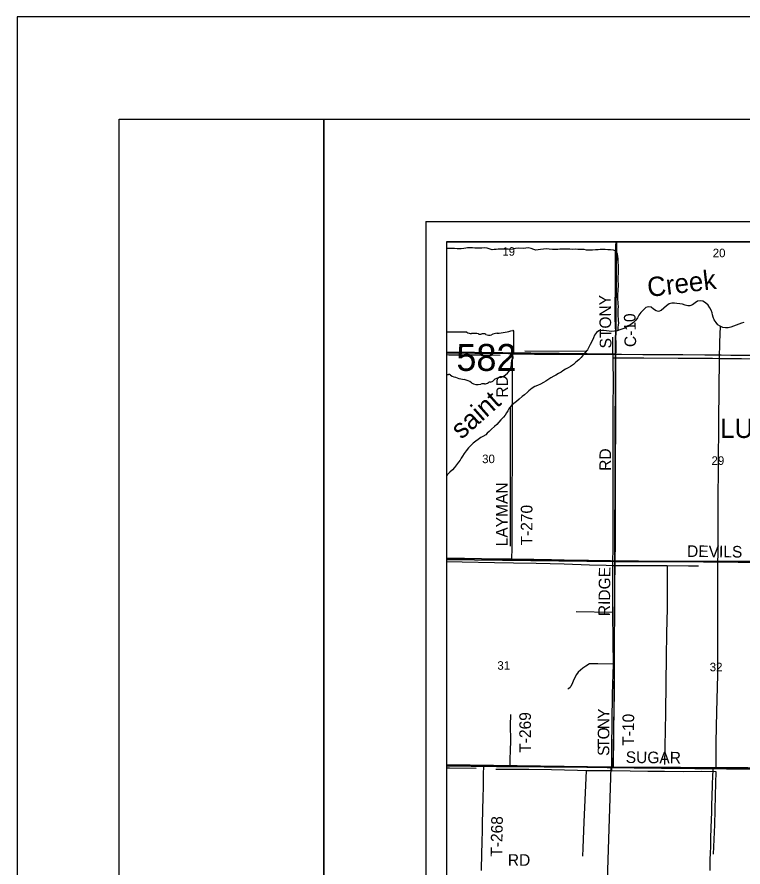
# Model space of a CAD drawing. Extents: x -8.3 to 42.1, y 0 to 22.
# Drawn here: x 0 to 3.551, y 17.841 to 22 of the extents above; entities that cross this region are included whole.
import ezdxf

# ---------------------------------------------------------------- set-up
doc = ezdxf.new("R2010")
doc.units = 0
for name, color, linetype in [('Default', 7, 'Continuous'), ('GM_X_Corporation_Text', 7, 'Continuous'), ('GM_X_County_Road', 7, 'Continuous'), ('GM_X_County_Road_Text', 7, 'Continuous'), ('GM_X_Major_River', 7, 'Continuous'), ('GM_X_Major_River_Text', 7, 'Continuous'), ('GM_X_Minor_River', 7, 'Continuous'), ('GM_X_Section', 7, 'Continuous'), ('GM_X_Section_Text', 7, 'Continuous'), ('GM_X_State_Location', 7, 'Continuous'), ('GM_X_State_Route', 7, 'Continuous'), ('GM_X_State_Shield', 7, 'Continuous'), ('GM_X_Township_Road', 7, 'Continuous'), ('GM_X_Township_Road_Text', 7, 'Continuous'), ('SH_Border', 7, 'Continuous'), ('SH_Cut_Line', 7, 'Continuous'), ('SH_Data', 7, 'Continuous')]:
    doc.layers.add(name, color=color, linetype=linetype)

msp = doc.modelspace()

# ---------------------------------------------------------------- linework, layer by layer
at = {"layer": 'Default'}
for points in [[(2.9318, 20.9), (2.1, 20.9), (2.1, 20.3595), (2.9276, 20.3504)], [(3.9394, 20.9), (2.9318, 20.9), (2.9276, 20.3504), (3.938, 20.3445)], [(2.1, 20.3595), (2.1, 19.3455), (2.9241, 19.3359), (2.9276, 20.3504)], [(2.1, 19.3455), (2.1, 18.3401), (2.9069, 18.3295), (2.9164, 18.3298), (2.9226, 18.6969), (2.9241, 19.3359)], [(2.1, 18.3401), (2.1, 17.3208), (2.8735, 17.321), (2.9069, 18.3295)]]:
    msp.add_lwpolyline(points, close=True, dxfattribs=at)
at = {"layer": 'GM_X_County_Road'}
for points in [[(2.9293, 20.3498), (2.9297, 20.3553), (2.9298, 20.3569), (2.9299, 20.3589), (2.9299, 20.387), (2.9299, 20.41), (2.9296, 20.4274), (2.9286, 20.4542), (2.9271, 20.4921), (2.9263, 20.5238), (2.9265, 20.612), (2.9267, 20.6475), (2.9269, 20.7003), (2.9271, 20.7843), (2.9273, 20.8247), (2.9277, 20.8396), (2.9293, 20.8787), (2.9301, 20.9)], [(2.1, 18.3366), (2.1679, 18.3356), (2.2208, 18.3346), (2.2836, 18.3338)], [(2.2836, 18.3338), (2.286, 18.3337), (2.3451, 18.3333), (2.413, 18.3327)], [(2.413, 18.3327), (2.4259, 18.3326), (2.5129, 18.3323), (2.5782, 18.3318), (2.6652, 18.3311), (2.7274, 18.3303), (2.7864, 18.3294), (2.8362, 18.3288), (2.8859, 18.328), (2.9185, 18.3276)], [(2.9185, 18.3276), (2.9325, 18.3274), (3.0195, 18.3264), (3.0662, 18.3259), (3.1532, 18.325), (3.234, 18.3242), (3.3148, 18.3234), (3.3583, 18.3229), (3.4054, 18.3223)], [(3.4054, 18.3223), (3.4174, 18.3222), (3.4702, 18.3219), (3.5199, 18.3217), (3.6194, 18.3209), (3.6878, 18.3206), (3.7468, 18.32), (3.7904, 18.3196), (3.8401, 18.319), (3.8898, 18.3182), (3.9079, 18.3179)]]:
    msp.add_lwpolyline(points, dxfattribs=at)
at = {"layer": 'GM_X_Major_River'}
for points in [[(3.5432, 20.5019), (3.531, 20.4968), (3.5172, 20.4917), (3.5038, 20.4867), (3.4908, 20.4827), (3.4779, 20.4795), (3.4653, 20.4783), (3.4525, 20.4804), (3.4386, 20.4875), (3.428, 20.493), (3.4192, 20.5058), (3.4103, 20.5188), (3.4049, 20.5319), (3.4024, 20.5433), (3.3999, 20.5529), (3.396, 20.5647), (3.3894, 20.5774), (3.3801, 20.5901), (3.3675, 20.6021), (3.3539, 20.6089), (3.3422, 20.6114), (3.3285, 20.6101), (3.3166, 20.602), (3.3035, 20.5908), (3.2913, 20.5865), (3.2818, 20.5867), (3.2689, 20.5907), (3.2546, 20.5944), (3.2417, 20.5962), (3.2281, 20.5987), (3.2152, 20.5993), (3.2023, 20.5992), (3.1893, 20.5957), (3.1763, 20.586), (3.1643, 20.5752), (3.1516, 20.5641), (3.1382, 20.5586), (3.1261, 20.5615), (3.1141, 20.5697), (3.1017, 20.5795), (3.0885, 20.5824), (3.0752, 20.5781), (3.0639, 20.5673), (3.0519, 20.5546), (3.0422, 20.5411), (3.0344, 20.5283), (3.0262, 20.5163), (3.0154, 20.5049), (3.0026, 20.4947), (2.9896, 20.4881), (2.9758, 20.4796), (2.9632, 20.4749), (2.9494, 20.4695), (2.9356, 20.4645), (2.9227, 20.462), (2.9094, 20.4615), (2.8961, 20.4622), (2.8836, 20.4639), (2.8696, 20.4661), (2.8598, 20.4663), (2.8465, 20.4639), (2.8338, 20.4569), (2.8244, 20.4434), (2.8196, 20.4309), (2.8145, 20.4185), (2.8042, 20.3982), (2.7975, 20.3846), (2.7901, 20.3722), (2.7792, 20.3587), (2.7691, 20.3464), (2.759, 20.3344), (2.7474, 20.3225), (2.7339, 20.3117), (2.7216, 20.3002), (2.7077, 20.2906), (2.6951, 20.284), (2.6832, 20.2766), (2.6701, 20.2681), (2.6611, 20.2621), (2.6484, 20.2551), (2.6353, 20.2477), (2.6255, 20.2432), (2.6115, 20.2346), (2.5972, 20.2254), (2.5872, 20.2184), (2.5745, 20.211), (2.5604, 20.2037), (2.5454, 20.1968), (2.5336, 20.1917), (2.5202, 20.184), (2.503, 20.1702), (2.4977, 20.1649), (2.4821, 20.1518), (2.4708, 20.1423), (2.4562, 20.1308), (2.4427, 20.1193), (2.4307, 20.1093), (2.418, 20.0989), (2.4071, 20.0854), (2.4, 20.073), (2.3949, 20.0628)], [(3.5549, 20.5055), (3.5432, 20.5019)], [(2.3949, 20.0628), (2.3879, 20.0516), (2.379, 20.0415), (2.3666, 20.0295), (2.3573, 20.0176), (2.3476, 20.006), (2.336, 19.9963), (2.3217, 19.9833), (2.3101, 19.9717), (2.3005, 19.9632), (2.2929, 19.9557), (2.2789, 19.9472), (2.2693, 19.9421), (2.2563, 19.9332), (2.2436, 19.9251), (2.2312, 19.9147), (2.2196, 19.9039), (2.208, 19.8916), (2.1975, 19.8777), (2.187, 19.8646), (2.1788, 19.8507), (2.1733, 19.8409), (2.1671, 19.8312), (2.16, 19.8214), (2.1402, 19.796), (2.1294, 19.784), (2.117, 19.7732), (2.1046, 19.7602), (2.1, 19.7542)]]:
    msp.add_lwpolyline(points, dxfattribs=at)
at = {"layer": 'GM_X_Minor_River'}
for points in [[(2.9408, 20.4663), (2.9412, 20.4816), (2.9423, 20.4919), (2.943, 20.504), (2.9429, 20.5143), (2.9417, 20.5238), (2.9405, 20.5364), (2.9401, 20.5482), (2.9407, 20.5687), (2.9415, 20.5839), (2.9411, 20.5965), (2.9398, 20.606), (2.9386, 20.6159), (2.9385, 20.6254), (2.9388, 20.6368), (2.9395, 20.6475), (2.9406, 20.6573), (2.9409, 20.6687), (2.9424, 20.6824), (2.9424, 20.6949), (2.9412, 20.7079), (2.9408, 20.7193), (2.9404, 20.7315), (2.9418, 20.7421), (2.9425, 20.7645), (2.9421, 20.7774), (2.9416, 20.7873), (2.9407, 20.7968), (2.9407, 20.8086), (2.9402, 20.8189), (2.9394, 20.8288), (2.9367, 20.8418), (2.9306, 20.8545), (2.9182, 20.8583), (2.9023, 20.8603), (2.8905, 20.8603), (2.8769, 20.8618), (2.8629, 20.8626), (2.853, 20.8621), (2.8431, 20.8612), (2.8298, 20.8612), (2.8157, 20.8594), (2.7994, 20.8591), (2.7857, 20.8598), (2.774, 20.8617), (2.757, 20.8626), (2.7433, 20.8626), (2.73, 20.8633), (2.7194, 20.8629), (2.7039, 20.8637), (2.6932, 20.864), (2.6807, 20.8636), (2.6659, 20.8633), (2.6553, 20.8632), (2.645, 20.8631), (2.6321, 20.8631), (2.6196, 20.8631), (2.6033, 20.8647), (2.5896, 20.8651), (2.5752, 20.8644), (2.56, 20.8621), (2.5493, 20.8609), (2.5379, 20.8597), (2.5273, 20.8631), (2.5149, 20.8669), (2.4998, 20.8699), (2.4892, 20.8687), (2.4793, 20.8679), (2.455, 20.8686), (2.439, 20.8671), (2.426, 20.8648), (2.4119, 20.863), (2.4024, 20.8632), (2.393, 20.8635), (2.3816, 20.8642), (2.3664, 20.8646), (2.3543, 20.8639), (2.3443, 20.8626), (2.3341, 20.8622), (2.3238, 20.8609), (2.3099, 20.8651), (2.2989, 20.8681), (2.2854, 20.8708), (2.2728, 20.8696), (2.2606, 20.8688), (2.2511, 20.8683), (2.239, 20.8687), (2.228, 20.8701), (2.217, 20.8708), (2.2041, 20.8697), (2.1946, 20.8684), (2.185, 20.8668), (2.1725, 20.866), (2.1619, 20.866), (2.1524, 20.8662), (2.1402, 20.867), (2.1266, 20.8673), (2.1122, 20.8674), (2.1011, 20.8669), (2.1, 20.8669)], [(3.4386, 20.4875), (3.4368, 20.407), (3.4346, 20.3291), (3.432, 20.025), (3.4301, 19.8011), (3.4284, 19.6339), (3.4278, 19.5313), (3.4273, 19.3971), (3.4256, 19.3078), (3.4261, 19.1793), (3.4261, 19.0481), (3.4259, 18.9208), (3.4265, 18.7809), (3.4213, 18.6001), (3.4186, 18.4519), (3.4174, 18.3283)], [(2.9122, 20.4334), (2.9132, 20.3646), (2.9142, 20.3307), (2.9154, 20.2022), (2.9145, 20.1033), (2.9146, 19.9851), (2.9147, 19.8307), (2.915, 19.7091), (2.914, 19.565), (2.9136, 19.4172), (2.9122, 19.3164), (2.9134, 19.1978), (2.9132, 19.0864), (2.9138, 18.9454), (2.9152, 18.8339), (2.9117, 18.6873), (2.9101, 18.5505), (2.9084, 18.4254), (2.9075, 18.3125)], [(2.3626, 20.3439), (2.2776, 20.3459), (2.1125, 20.3461), (2.1, 20.3462)], [(2.7827, 20.3631), (2.4835, 20.3644)], [(2.915, 20.3318), (3.0653, 20.3317), (3.2342, 20.3307), (3.4023, 20.3304), (3.4346, 20.3291), (3.5439, 20.329)], [(3.5439, 20.329), (3.6686, 20.3274), (3.7712, 20.3284), (3.9117, 20.3272)], [(2.4118, 20.0912), (2.4121, 19.8296), (2.4128, 19.6558), (2.4115, 19.411)], [(2.1, 19.3356), (2.1774, 19.3337), (2.336, 19.3303), (2.4278, 19.3284), (2.5394, 19.3275), (2.6767, 19.3236), (2.8003, 19.3193), (2.8815, 19.3173), (2.9122, 19.3164), (2.9999, 19.3166), (3.0952, 19.3165), (3.1806, 19.3167), (3.2849, 19.3153), (3.3339, 19.3142)], [(3.1806, 19.3167), (3.1795, 19.1065), (3.1772, 18.9857), (3.175, 18.8683), (3.1741, 18.7421), (3.1721, 18.5935), (3.1686, 18.4313), (3.1669, 18.3424)], [(2.9132, 19.0864), (2.7349, 19.0893)], [(2.9152, 18.8339), (2.8408, 18.8357), (2.8009, 18.8357), (2.7816, 18.8237), (2.7669, 18.8131), (2.7443, 18.7936), (2.7364, 18.7836), (2.7227, 18.7558), (2.7158, 18.7378), (2.7097, 18.7258), (2.705, 18.7198), (2.6996, 18.7147), (2.6942, 18.7118)], [(2.2461, 18.3224), (2.1153, 18.3246), (2.1, 18.3246)], [(2.3429, 18.3192), (2.5034, 18.3192), (2.6146, 18.3175), (2.7417, 18.3154), (2.7842, 18.3134), (2.8639, 18.313), (2.9075, 18.3125), (2.9986, 18.3111), (3.0855, 18.3105), (3.1663, 18.3093), (3.2578, 18.3082), (3.3496, 18.3094), (3.4187, 18.3078), (3.415, 18.1904), (3.4109, 18.0468), (3.4057, 17.9044)], [(2.7842, 18.3134), (2.7788, 18.2045), (2.7725, 18.0624), (2.7673, 17.9329), (2.7661, 17.8934)]]:
    msp.add_lwpolyline(points, dxfattribs=at)
at = {"layer": 'GM_X_Section'}
for points in [[(3.938, 20.3445), (3.9295, 19.335), (2.9241, 19.3359), (2.9276, 20.3504)], [(2.9241, 19.3359), (3.9295, 19.335), (3.9115, 18.3241), (3.9047, 18.3241), (2.9164, 18.3298), (2.9226, 18.6969)], [(2.9069, 18.3295), (2.9164, 18.3298), (3.9047, 18.3241), (3.8739, 17.3266), (2.8735, 17.321)]]:
    msp.add_lwpolyline(points, close=True, dxfattribs=at)
at = {"layer": 'GM_X_State_Route'}
msp.add_lwpolyline([(2.1, 20.3563), (2.175, 20.356), (2.2388, 20.3557), (2.3678, 20.355), (2.3911, 20.3546), (2.4048, 20.3539), (2.4173, 20.3534), (2.4243, 20.3528), (2.4291, 20.3523), (2.4331, 20.352), (2.4461, 20.3518), (2.4694, 20.3512), (2.5315, 20.3505), (2.6015, 20.3501), (2.6341, 20.3498), (2.7056, 20.3496), (2.7491, 20.3498), (2.8081, 20.35), (2.8921, 20.3498), (2.9293, 20.3498), (2.9573, 20.3496), (3.0614, 20.3491), (3.1283, 20.3489), (3.2572, 20.3479), (3.3645, 20.3471), (3.4437, 20.3465), (3.4919, 20.346), (3.5385, 20.3457), (3.6084, 20.3454)], dxfattribs=at)
at = {"layer": 'GM_X_State_Shield'}
for p, q in [((2.1, 20.4543), (2.1, 20.2542)), ((2.1998, 20.4578), (2.1032, 20.4578)), ((2.4296, 20.358), (2.4296, 20.4627)), ((2.4296, 20.3581), (2.4296, 20.358))]:
    msp.add_line(p, q, dxfattribs=at)
for centre, major_axis, start_param, end_param in [((2.3122, 20.7306), (0.3495, 0), 4.814394, 5.042369), ((2.4259, 20.4631), (0.00367, 0), 6.141152, 7.989035), ((2.1038, 20.4547), (0.00382, 0), 1.712693, 3.28349), ((2.2228, 20.481), (0.037, 0), 4.042523, 4.731795), ((2.235, 20.3454), (0.133, 0), 1.404758, 1.657858), ((2.2652, 20.4558), (0.0107, 0), 3.836095, 5.185415), ((2.2809, 20.4326), (0.0222, 0), 0.950623, 2.079405), ((2.3096, 20.4644), (0.0267, 0), 4.081561, 5.145723), ((2.3568, 20.3966), (0.0703, 0), 1.699011, 2.107814), ((2.4287, 20.3503), (0.00568, 0), 1.883978, 3.671073), ((2.3926, 20.3371), (0.0341, 0), 5.934695, 6.695948), ((2.4257, 20.3576), (0.00393, 0), 5.05454, 6.418171), ((2.3318, 20.3009), (0.0874, 0), 5.101752, 6.440018), ((2.4427, 20.3142), (0.0248, 0), 2.387724, 3.262537), ((2.1038, 20.2537), (0.00385, 0), 3.00124, 4.508301), ((2.1044, 20.2742), (0.0294, 0), 4.665946, 4.897461), ((2.1104, 20.2426), (0.0106, 0), 0.519207, 1.627899), ((2.2442, 20.4224), (0.2524, 0), 4.195997, 4.488961), ((2.169, 20.1643), (0.079, 0), 0.823519, 1.323587), ((2.3112, 20.2073), (0.00752, 0), 1.147584, 2.315152), ((2.308, 20.2348), (0.0282, 0), 4.937069, 5.64225), ((2.3686, 20.198), (0.0479, 0), 1.647645, 2.488434), ((2.2544, 20.2416), (0.0501, 0), 4.026481, 4.996735), ((2.2834, 20.1725), (0.0412, 0), 1.495662, 1.94098), ((2.287, 20.2267), (0.0267, 0), 4.691044, 5.507374)]:
    msp.add_ellipse(centre, major_axis=major_axis, ratio=0.8, start_param=start_param, end_param=end_param, dxfattribs=at)
at = {"layer": 'GM_X_Township_Road'}
for points in [[(3.9382, 20.9), (2.1, 20.9), (2.1, 15.312)], [(2.4209, 19.348), (2.421, 19.3533), (2.4216, 19.3953), (2.4219, 19.4668), (2.4222, 19.5119), (2.4222, 19.5803), (2.4224, 19.6394), (2.4227, 19.7187), (2.4231, 19.784), (2.4232, 19.8166), (2.4237, 19.8975), (2.4241, 19.9441), (2.4239, 19.983), (2.4241, 20.0032), (2.4243, 20.0374), (2.4241, 20.0762), (2.4235, 20.1073), (2.4232, 20.1477), (2.4234, 20.2006), (2.4236, 20.2519), (2.4241, 20.2954), (2.4242, 20.3343), (2.4243, 20.3481), (2.4243, 20.3528)], [(2.9261, 19.3397), (2.9261, 19.346), (2.9264, 19.369), (2.9267, 19.3964), (2.9271, 19.4337), (2.9273, 19.4872), (2.9273, 19.5525), (2.9275, 19.5947), (2.9274, 19.6277), (2.9277, 19.6681), (2.9278, 19.7023), (2.928, 19.7328), (2.928, 19.7726), (2.9279, 19.8323), (2.9281, 19.8839), (2.9286, 19.9324), (2.929, 19.9815), (2.9291, 20.0499), (2.929, 20.1246), (2.9288, 20.1687), (2.9288, 20.2322), (2.929, 20.2751), (2.9291, 20.3174), (2.929, 20.3412), (2.929, 20.3429), (2.9291, 20.3443), (2.9293, 20.3498)], [(2.1, 19.3528), (2.1388, 19.3523), (2.1885, 19.3515), (2.2724, 19.3503), (2.3284, 19.3494), (2.4209, 19.348)], [(2.4209, 19.348), (2.4341, 19.3478), (2.5273, 19.3465), (2.577, 19.3454), (2.6143, 19.3449), (2.6765, 19.3436), (2.7417, 19.3426), (2.7946, 19.3416), (2.8319, 19.3411), (2.8598, 19.3405), (2.9033, 19.34), (2.9261, 19.3397)], [(2.9185, 18.3276), (2.9183, 18.3353), (2.918, 18.3446), (2.9181, 18.382), (2.9185, 18.4379), (2.919, 18.497), (2.9194, 18.5436), (2.9201, 18.612), (2.9207, 18.6835), (2.9208, 18.7146), (2.9219, 18.7892), (2.9224, 18.8202), (2.9226, 18.8451), (2.9226, 18.9042), (2.9227, 18.9414), (2.9222, 18.9943), (2.922, 19.0254), (2.9226, 19.0907), (2.9235, 19.1404), (2.9243, 19.1901), (2.9248, 19.2492), (2.9252, 19.2896), (2.9261, 19.3397)], [(2.9261, 19.3397), (2.9375, 19.3396), (2.9841, 19.3391), (3.0401, 19.3383), (3.1084, 19.3373), (3.1799, 19.3366), (3.2328, 19.3359), (3.2887, 19.3353), (3.3042, 19.3352), (3.3571, 19.3345), (3.3882, 19.334), (3.3975, 19.3338), (3.4348, 19.3335), (3.528, 19.3324), (3.5808, 19.3318), (3.6213, 19.3314), (3.6772, 19.3307), (3.7704, 19.3296), (3.7984, 19.3292), (3.8326, 19.3287), (3.8978, 19.328), (3.9227, 19.3278), (3.9246, 19.3278)], [(2.413, 18.3327), (2.413, 18.3381), (2.4129, 18.36), (2.414, 18.4192), (2.4149, 18.45), (2.4148, 18.4694), (2.4139, 18.5254), (2.4142, 18.5504), (2.4151, 18.5691), (2.4153, 18.5785), (2.4151, 18.5869)], [(2.2719, 17.823), (2.2721, 17.8314), (2.2725, 17.8501), (2.2734, 17.8843), (2.274, 17.9155), (2.2748, 17.9528), (2.2766, 18.0307), (2.2776, 18.0712), (2.2782, 18.0992), (2.2787, 18.1241), (2.2796, 18.1771), (2.2811, 18.2363), (2.2818, 18.2643), (2.2823, 18.2954), (2.2825, 18.311), (2.2828, 18.3172), (2.283, 18.3236), (2.2834, 18.33), (2.2836, 18.3338)], [(3.3907, 17.8234), (3.3905, 17.8317), (3.3905, 17.8535), (3.391, 17.8784), (3.3918, 17.9064), (3.3932, 17.9436), (3.3944, 17.9841), (3.3957, 18.0307), (3.3971, 18.0742), (3.3982, 18.1053), (3.3994, 18.1395), (3.4025, 18.2389), (3.4039, 18.2918), (3.4045, 18.3073), (3.405, 18.3166), (3.4054, 18.3223)]]:
    msp.add_lwpolyline(points, dxfattribs=at)
at = {"layer": 'SH_Border'}
for points in [[(0.5, 21.5), (1.5, 21.5), (1.5, 0.5), (0.5, 0.5)], [(1.5, 21.5), (33.5, 21.5), (33.5, 0.5), (1.5, 0.5)]]:
    msp.add_lwpolyline(points, close=True, dxfattribs=at)
at = {"layer": 'SH_Cut_Line'}
msp.add_lwpolyline([(0, 0), (34, 0), (34, 22), (0, 22)], close=True, dxfattribs=at)
msp.add_lwpolyline([(7.9572, 20.9), (2.1, 20.9), (2.1, 14.1)], dxfattribs=at)
at = {"layer": 'SH_Data'}
for p, q in [((2, 21), (9, 21)), ((2, 21), (2, 14)), ((2.1, 20.9), (2.1, 14.1)), ((2.1, 20.9), (8.9, 20.9))]:
    msp.add_line(p, q, dxfattribs=at)

# ---------------------------------------------------------------- texts
at = {"layer": 'GM_X_Corporation_Text'}
msp.add_text('LUCKEY', height=0.0947, rotation=0, dxfattribs=at).set_placement((3.4392, 19.9402))
at = {"layer": 'GM_X_County_Road_Text'}
for s, rotation, p in [('STONY', 90.8095, (2.9077, 20.3787)), ('C-10', 91.3251, (3.0288, 20.3855)), ('SUGAR', 359.3933, (2.9773, 18.35))]:
    msp.add_text(s, height=0.05682, rotation=rotation, dxfattribs=at).set_placement(p)
at = {"layer": 'GM_X_Major_River_Text'}
for s, height, rotation, p in [('Creek', 0.09476, 6.9145, (3.0886, 20.6296)), ('saint', 0.09475, 41.5112, (2.1736, 19.93))]:
    msp.add_text(s, height=height, rotation=rotation, dxfattribs=at).set_placement(p)
at = {"layer": 'GM_X_Section_Text'}
for s, p in [('19', (2.3738, 20.8319)), ('20', (3.403, 20.8244)), ('30', (2.2751, 19.8169)), ('29', (3.3971, 19.8085)), ('31', (2.3496, 18.806)), ('32', (3.3884, 18.7985))]:
    msp.add_text(s, height=0.04186, rotation=0, dxfattribs=at).set_placement(p)
at = {"layer": 'GM_X_State_Location'}
msp.add_text('582', height=0.000189, rotation=0, dxfattribs=at).set_placement((2.1759, 20.3196))
for s in ['s', 'r']:
    msp.add_text(s, height=0.000189, dxfattribs=at).set_placement((2.2427, 20.3334))
at = {"layer": 'GM_X_State_Shield'}
msp.add_text('582', height=0.13184, dxfattribs=at).set_placement((2.149, 20.2683))
at = {"layer": 'GM_X_Township_Road_Text'}
for s, height, rotation, p in [('RD', 0.05682, 90, (2.4012, 20.1376)), ('RD', 0.05682, 89.5104, (2.9052, 19.7792)), ('LAYMAN', 0.05682, 90, (2.4004, 19.4101)), ('T-270', 0.05682, 90, (2.5212, 19.4143)), ('DEVILS', 0.05682, 359.2281, (3.2771, 19.3583)), ('RIDGE', 0.05682, 89.3255, (2.9002, 19.0679)), ('T-269', 0.05682, 90, (2.5137, 18.4001)), ('Y', 0.0568, 89.1476, (2.8975, 18.5651)), ('N', 0.0568, 89.7916, (2.8973, 18.5152)), ('T-10', 0.05682, 89.6467, (3.0178, 18.4342)), ('O', 0.0568, 89.7887, (2.8972, 18.4652)), ('T', 0.0568, 89.79, (2.897, 18.4227)), ('S', 0.0568, 89.7909, (2.8969, 18.3844)), ('T-268', 0.05682, 88.8721, (2.3728, 17.8907)), ('RD', 0.05682, 0, (2.4009, 17.8467))]:
    msp.add_text(s, height=height, rotation=rotation, dxfattribs=at).set_placement(p)

doc.saveas('drawing.dxf')
